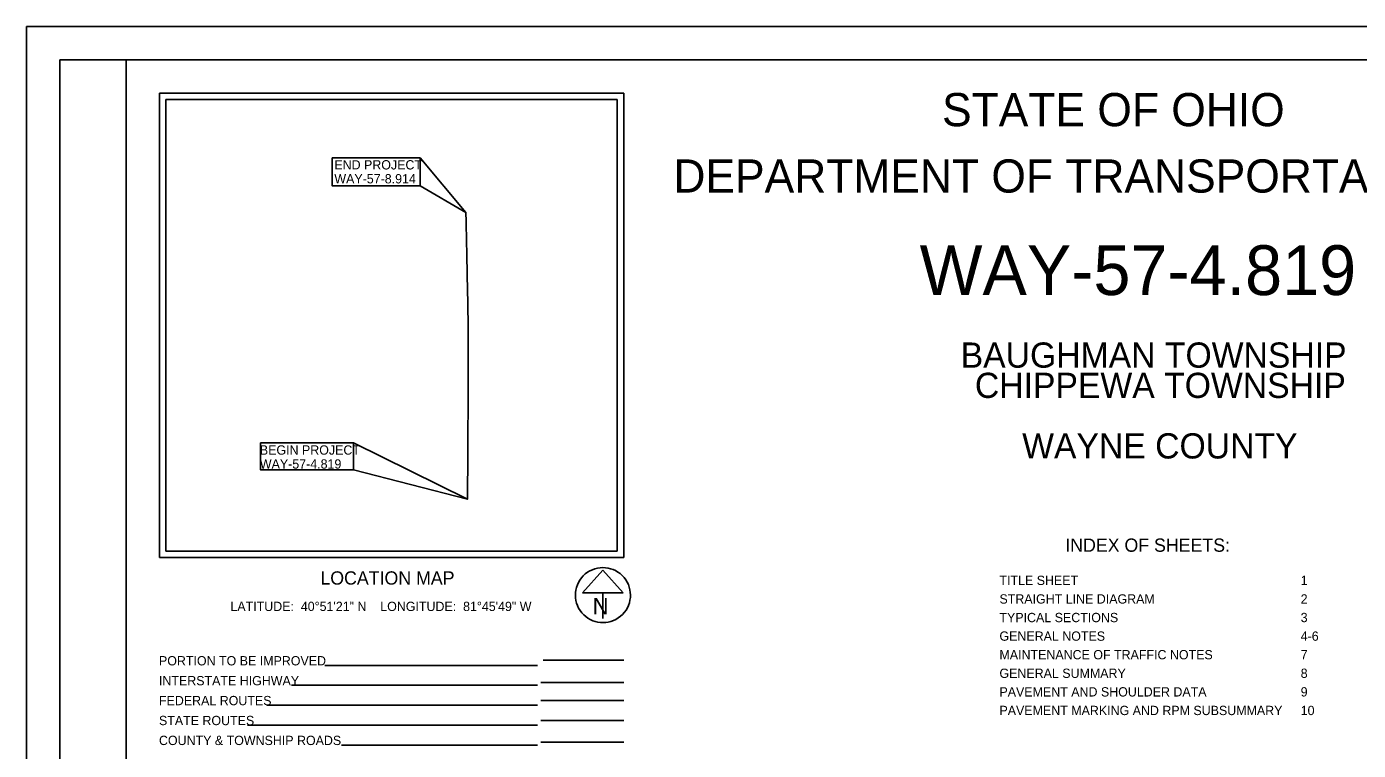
# Model space of a CAD drawing. Extents: x 0 to 170000, y 0 to 110000.
# Drawn here: x 0 to 100344, y 55484 to 110000 of the extents above; entities that cross this region are included whole.
import ezdxf

# ---------------------------------------------------------------- set-up
doc = ezdxf.new("R2010")
doc.units = 0
for name, color, linetype in [('SH_Border', 7, 'Continuous'), ('SH_Cut_Line', 7, 'Continuous'), ('SH_Data', 7, 'Continuous'), ('SH_Text', 7, 'Continuous')]:
    doc.layers.add(name, color=color, linetype=linetype)

msp = doc.modelspace()

# ---------------------------------------------------------------- linework, layer by layer
at = {"layer": 'SH_Border'}
for points in [[(2500, 107500), (7500, 107500), (7500, 2500), (2500, 2500)], [(7500, 107500), (167500, 107500), (167500, 2500), (7500, 2500)]]:
    msp.add_lwpolyline(points, close=True, dxfattribs=at)
at = {"layer": 'SH_Cut_Line'}
msp.add_lwpolyline([(0, 0), (170000, 0), (170000, 110000), (0, 110000)], close=True, dxfattribs=at)
at = {"layer": 'SH_Data'}
for p, q in [((10000, 105000), (45000, 105000)), ((10000, 105000), (10000, 70000)), ((10500, 104500), (10500, 70500)), ((10500, 104500), (44500, 104500)), ((44500, 104500), (44500, 70500)), ((45000, 105000), (45000, 70000)), ((10500, 70500), (44500, 70500)), ((10500, 70500), (10500, 70500)), ((10000, 70000), (45000, 70000)), ((43423, 69045), (41885, 67339)), ((44960, 67339), (43423, 69045)), ((41885, 67339), (44960, 67339)), ((43423, 67339), (43423, 65405)), ((43423, 67177), (43423, 67177)), ((43423, 67177), (43423, 67177)), ((38913, 62277), (45000, 62277)), ((38500, 61883), (22468, 61883)), ((38500, 60383), (19948, 60383)), ((45000, 60604), (38750, 60604)), ((45000, 59245), (38750, 59245)), ((38500, 58883), (18096, 58883)), ((38500, 57383), (16644, 57383)), ((45000, 57745), (38750, 57745)), ((38500, 55883), (23726, 55883)), ((45000, 56112), (38750, 56112))]:
    msp.add_line(p, q, dxfattribs=at)
msp.add_lwpolyline([(33216, 74398), (33221, 74879), (33224, 75256), (33228, 75880), (33232, 76422), (33233, 76866), (33236, 77024), (33236, 77467), (33241, 77729), (33241, 78041), (33246, 78729), (33247, 78992), (33250, 79467), (33252, 79729), (33253, 79992), (33255, 80204), (33258, 80548), (33257, 80679), (33258, 80858), (33259, 80936), (33261, 81204), (33261, 81335), (33262, 81499), (33263, 81679), (33264, 82024), (33265, 82162), (33266, 82425), (33271, 83434), (33276, 84287), (33278, 84714), (33279, 85086), (33279, 85649), (33277, 86026), (33277, 86338), (33276, 86518), (33276, 86747), (33275, 87108), (33271, 87445), (33269, 87699), (33261, 88109), (33256, 88387), (33247, 88847), (33241, 89159), (33236, 89437), (33227, 89913), (33222, 90122), (33214, 90454), (33203, 91028), (33199, 91306), (33189, 91666), (33185, 91814), (33183, 91962), (33177, 92240), (33173, 92404), (33169, 92706), (33169, 92748), (33168, 92795), (33162, 93175), (33153, 93535), (33145, 93929), (33133, 94454), (33128, 94634), (33127, 94732), (33123, 94912), (33110, 95558), (33104, 95772), (33099, 95989)], dxfattribs=at)
msp.add_arc((43423, 67177), 2074, 129.77984, 129.76332, dxfattribs=at)
at = {"layer": 'SH_Text'}
for points in [[(23012, 100116), (29642, 100116), (29642, 98016), (23012, 98016)], [(29642, 100116), (33099, 95989), (29642, 98016)], [(17625, 78648), (24623, 78648), (24623, 76603), (17625, 76603)], [(24623, 78648), (33216, 74398), (24623, 76603)]]:
    msp.add_lwpolyline(points, close=True, dxfattribs=at)

# ---------------------------------------------------------------- texts
at = {"layer": 'SH_Data'}
msp.add_text('N', height=1250, dxfattribs=at).set_placement((42646, 65720))
at = {"layer": 'SH_Text'}
for s, height, p in [('STATE OF OHIO', 2500, (68975, 102500)), ('END PROJECT', 700, (23187, 99241)), ('DEPARTMENT OF TRANSPORTATION', 2500, (48733, 97500)), ('WAY-57-8.914', 700, (23187, 98191)), ('WAY-57-4.819', 3750, (67288, 89782)), ('BAUGHMAN TOWNSHIP', 1900, (70380, 84309)), ('CHIPPEWA TOWNSHIP', 1900, (71450, 82029)), ('WAYNE COUNTY', 1900, (75011, 77469)), ('BEGIN PROJECT', 700, (17574, 77758)), ('WAY-57-4.819', 700, (17574, 76708)), ('INDEX OF SHEETS:', 1000, (78262, 70442)), ('LOCATION MAP', 1000, (22135, 67969)), ('TITLE SHEET', 700, (73301, 67940)), ('1', 700, (95999, 67940)), ('STRAIGHT LINE DIAGRAM', 700, (73301, 66540)), ('2', 700, (95999, 66540)), ('LATITUDE:  40°51\'21" N    LONGITUDE:  81°45\'49" W', 700, (15355, 65979)), ('TYPICAL SECTIONS', 700, (73301, 65140)), ('3', 700, (95999, 65140)), ('GENERAL NOTES', 700, (73301, 63740)), ('4-6', 700, (95999, 63740)), ('PORTION TO BE IMPROVED', 700, (9972, 61883)), ('MAINTENANCE OF TRAFFIC NOTES', 700, (73301, 62340)), ('7', 700, (95999, 62340)), ('GENERAL SUMMARY', 700, (73301, 60940)), ('8', 700, (95999, 60940)), ('INTERSTATE HIGHWAY', 700, (9972, 60383)), ('PAVEMENT AND SHOULDER DATA', 700, (73301, 59540)), ('9', 700, (95999, 59540)), ('FEDERAL ROUTES', 700, (9972, 58883)), ('PAVEMENT MARKING AND RPM SUBSUMMARY', 700, (73301, 58140)), ('10', 700, (95999, 58140)), ('STATE ROUTES', 700, (9972, 57383)), ('COUNTY & TOWNSHIP ROADS', 700, (9972, 55883))]:
    msp.add_text(s, height=height, dxfattribs=at).set_placement(p)

doc.saveas('drawing.dxf')
